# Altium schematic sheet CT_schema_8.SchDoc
size 226 x 144 mm
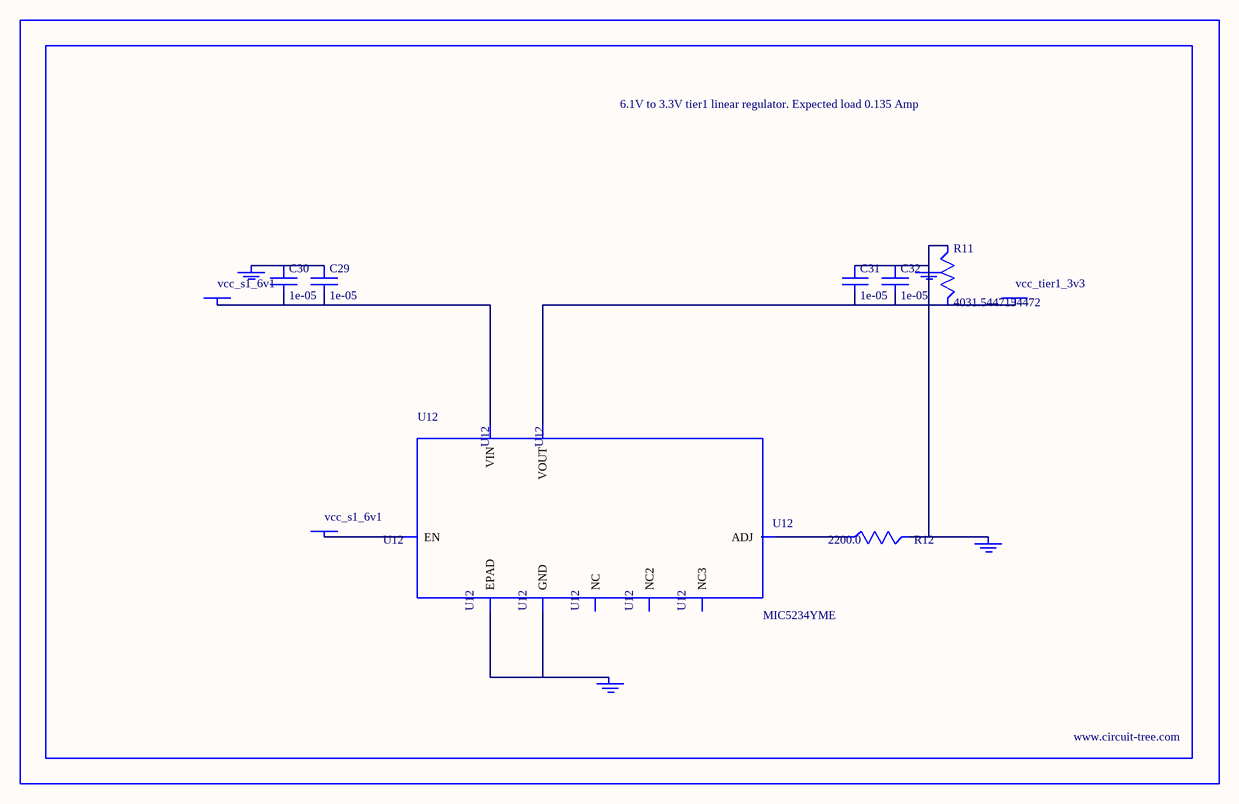
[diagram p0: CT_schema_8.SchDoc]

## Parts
BORDER7  (no value)
C29  1e-05  [C1210]
C30  1e-05  [C1210]
C31  1e-05  [C1210]
C32  1e-05  [C1210]
GND_INSTANCE_7_0  (no value)
GND_INSTANCE_7_1  (no value)
GND_INSTANCE_7_2  (no value)
GND_INSTANCE_7_3  (no value)
POWER_INSTANCE_7_0  vcc_tier1_3v3
POWER_INSTANCE_7_1  vcc_s1_6v1
POWER_INSTANCE_7_2  vcc_s1_6v1
R11  4031.5447154472  [R0603]
R12  2200.0  [R0603]
U12  MIC5234YME  [SOIC-8_EP]

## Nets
NetC29_1: C29.1 C30.1 GND_INSTANCE_7_3.0(GND)
NetC29_2: C29.2 C30.2 POWER_INSTANCE_7_2.0(PWR) U12.8(VIN)
NetC31_1: C31.1 C32.1 GND_INSTANCE_7_0.0(GND) GND_INSTANCE_7_1.0(GND) R11.1 R12.2
NetC31_2: C31.2 C32.2 POWER_INSTANCE_7_0.0(PWR) R11.2 U12.1(VOUT)
NetGND_INSTANCE_7_2_0: GND_INSTANCE_7_2.0(GND) U12.7(GND) U12.EPAD
NetPOWER_INSTANCE_7_1_0: POWER_INSTANCE_7_1.0(PWR) U12.5(EN)
NetR12_1: R12.1 U12.4(ADJ)

Not connected (* = marked no-connect by the designer): U12 2(NC) 3(NC2) 6(NC3)

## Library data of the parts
BORDER7 = BORDER_PAGE7
C29-C32 = C1210C106K5PACTU
GND_INSTANCE_7_0-GND_INSTANCE_7_3 = GND
POWER_INSTANCE_7_0-POWER_INSTANCE_7_2 = PWR
R11 = R11
R12 = RC0603JR-072K2L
